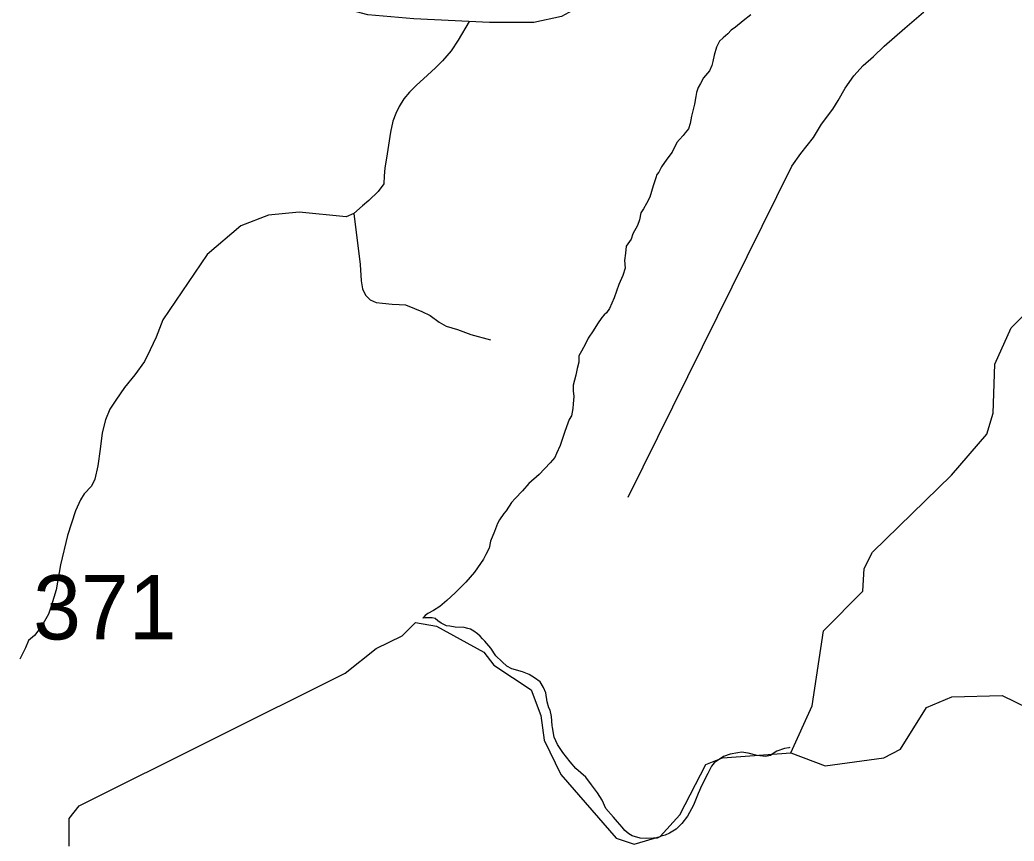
# Model space of a CAD drawing. Extents: x 2001466 to 2224147, y 644118 to 847247.
# Drawn here: x 2032460 to 2037534, y 689045 to 693236 of the extents above; entities that cross this region are included whole.
import ezdxf

# ---------------------------------------------------------------- set-up
doc = ezdxf.new("R2010")
doc.units = 0
for name, color, linetype in [('Exist Hydrographic Creek Single Shore', 7, 'Continuous'), ('Exist Hydrographic Misc Water Feature', 7, 'Continuous'), ('Exist Road Non-System Type 51', 7, 'Continuous'), ('Exist Road Secondary Structure Standard Bridge Number Label', 7, 'Continuous'), ('Exist Road Secondary Type 51 Attributed', 7, 'Continuous')]:
    doc.layers.add(name, color=color, linetype=linetype)

msp = doc.modelspace()

# ---------------------------------------------------------------- linework, layer by layer
at = {"layer": 'Exist Hydrographic Creek Single Shore'}
for points in [[(2032712.1, 689019), (2032712.1, 689160.1), (2032762.1, 689224.7), (2034120.2, 689902.4), (2034278.2, 690027.2), (2034411.1, 690093.4), (2034478.2, 690161), (2034586.2, 690142.3), (2034828.2, 690009.5), (2034878.2, 689942.8), (2035069.1, 689817.5), (2035119.2, 689685.3), (2035136.2, 689560.3), (2035220.1, 689384.6), (2035503, 689060.7), (2035595.1, 689029.2), (2035728.2, 689069.2), (2035828, 689178.7), (2035961.1, 689435.2), (2036045.2, 689469.6), (2036394.2, 689495.3)], [(2037215.8, 689780.5), (2037472.1, 689788.3), (2037605.2, 689723.3), (2037747.1, 689756.5), (2037946.2, 689949.3), (2038046.1, 689999.8), (2038229.2, 690022.3)], [(2036394.2, 689495.3), (2036569.1, 689429.4), (2036869.1, 689469.3), (2036953.2, 689513.5), (2037086, 689727.3), (2037215.8, 689780.5)]]:
    msp.add_lwpolyline(points, dxfattribs=at)
at = {"layer": 'Exist Hydrographic Misc Water Feature'}
for p, q in [((2037526.3, 691672.4), (2037803.4, 691955.3)), ((2036388.4, 689522.3), (2036384.5, 689520.3))]:
    msp.add_line(p, q, dxfattribs=at)
for points in [[(2036190.4, 693261.6), (2036150.4, 693231.6), (2036112.4, 693199.5), (2036090.3, 693183.5), (2036072.5, 693165.5), (2036048.5, 693143.6), (2036030.4, 693127.6), (2036014.4, 693097.5), (2036002.5, 693055.5), (2035996.6, 693023.5), (2035990.4, 693003.6), (2035978.5, 692975.6), (2035948.6, 692939.5), (2035932.6, 692911.5), (2035920.5, 692891.5), (2035912.5, 692865.5), (2035908.6, 692845.5), (2035902.7, 692805.5), (2035886.7, 692745.5), (2035880.7, 692707.5), (2035872.7, 692679.5), (2035854.7, 692659.5), (2035844.6, 692645.5), (2035826.8, 692625.5), (2035812.9, 692609.5), (2035788.9, 692561.5), (2035760.8, 692525.4), (2035734.9, 692485.4), (2035720.8, 692459.4), (2035710.7, 692447.4), (2035705, 692429.4), (2035691.1, 692389.4), (2035675.1, 692331.4), (2035657, 692299.4), (2035642.9, 692271.4), (2035628.9, 692251.4), (2035621.1, 692215.4), (2035611.1, 692187.4), (2035587.1, 692143.4), (2035579.1, 692117.4), (2035553.1, 692081.3), (2035551.2, 692045.4), (2035545.3, 692007.4), (2035549.2, 691969.4), (2035537.3, 691931.4), (2035517.2, 691885.4), (2035493.4, 691817.4), (2035469.4, 691763.4), (2035453.4, 691741.4), (2035441.3, 691731.4), (2035429.4, 691717.4), (2035407.5, 691685.3), (2035385.5, 691649.3), (2035359.5, 691611.4), (2035345.5, 691583.4), (2035325.4, 691545.3), (2035311.5, 691521.3), (2035311.5, 691489.3), (2035303.5, 691457.4), (2035297.6, 691423.4), (2035283.6, 691371.3), (2035283.6, 691343.4), (2035287.5, 691313.4), (2035283.6, 691277.3), (2035281.8, 691253.3)], [(2037214.6, 690912.3), (2037394.2, 691122), (2037427.2, 691229.6), (2037435.2, 691478.8), (2037518.3, 691664.2), (2037526.3, 691672.4)], [(2035281.8, 691253.3), (2035275.6, 691215.3), (2035263.7, 691197.4), (2035255.7, 691177.4), (2035241.6, 691135.3), (2035217.8, 691063.4), (2035197.9, 691023.4), (2035189.7, 691003.3), (2035165.7, 690975.3), (2035109.9, 690915.3), (2035057.9, 690869.3), (2035024, 690833.3), (2034987.9, 690793.2), (2034968, 690773.2), (2034942, 690731.2), (2034930.1, 690717.2), (2034908, 690685.2), (2034898.1, 690665.2), (2034882.1, 690625.2), (2034862.2, 690575.2), (2034854.2, 690539.2), (2034838.2, 690507.1), (2034826.1, 690483.2), (2034780.2, 690417.1), (2034736.3, 690367.2), (2034680.4, 690311.2), (2034638.3, 690273.1), (2034602.4, 690243.1), (2034570.4, 690221.1), (2034542.4, 690207), (2034528.4, 690197), (2034516.3, 690183)], [(2036394.2, 689495.3), (2036503.1, 689735.9), (2036561.1, 690118.6), (2036761.2, 690321.2), (2036769.2, 690435.9), (2036810.2, 690520.3), (2037214.6, 690912.3)], [(2036384.5, 689520.3), (2036362.6, 689518.3), (2036322.4, 689504.3), (2036304.6, 689492.3), (2036290.4, 689482.2), (2036264.6, 689476.2), (2036222.6, 689482.2), (2036176.4, 689494.2), (2036142.6, 689498.2), (2036124.5, 689496.1), (2036084.6, 689488.1), (2036050.7, 689476.1), (2036028.6, 689462.1), (2036002.5, 689444.1), (2035988.6, 689428.1), (2035970.5, 689390.1), (2035940.6, 689330), (2035920.7, 689288.1), (2035896.7, 689228), (2035866.8, 689172.1), (2035838.7, 689134.1), (2035809, 689106), (2035774.9, 689086), (2035752.8, 689076), (2035732.9, 689070), (2035712.8, 689060), (2035692.9, 689060), (2035658.9, 689057.9), (2035624.8, 689059.9), (2035584.8, 689071.9), (2035566.8, 689081.8), (2035546.9, 689099.9), (2035533, 689115.9), (2035509, 689143.8), (2035488.9, 689167.8), (2035450.7, 689211.8), (2035430.8, 689253.7), (2035406.9, 689291.7), (2035376.7, 689331.7), (2035348.8, 689371.7), (2035296.7, 689415.7), (2035268.9, 689449.6), (2035230.7, 689497.6), (2035202.6, 689537.6), (2035186.6, 689575.5), (2035178.6, 689625.5), (2035176.6, 689635.5), (2035172.7, 689681.6), (2035166.5, 689713.5), (2035158.7, 689725.5), (2035150.5, 689755.5), (2035144.6, 689801.5), (2035132.5, 689829.5), (2035114.5, 689857.5), (2035086.6, 689877.5), (2035058.5, 689895.4), (2035024.4, 689909.4), (2034970.5, 689923.4), (2034944.5, 689937.4), (2034920.5, 689959.3), (2034888.5, 689991.3), (2034862.4, 690029.3), (2034832.5, 690065.2), (2034820.4, 690077.2), (2034808.3, 690091.2), (2034794.4, 690103.2), (2034776.3, 690117.2), (2034760.3, 690127.2), (2034746.4, 690129.2), (2034726.5, 690135.1), (2034680.4, 690137.1), (2034654.3, 690141.1), (2034636.5, 690143.1), (2034610.4, 690157.1), (2034592.4, 690169.1), (2034578.4, 690181.1), (2034564.5, 690185.1), (2034542.4, 690185.1), (2034528.4, 690185), (2034516.3, 690183)]]:
    msp.add_lwpolyline(points, dxfattribs=at)
at = {"layer": 'Exist Road Non-System Type 51'}
for points in [[(2035564.2, 690800.7), (2036399, 692489.7), (2036444.9, 692553.8), (2036509, 692635.9), (2036550.8, 692703.8), (2036609, 692779.9), (2036634.9, 692823.9), (2036670.8, 692887.8), (2036714.8, 692949.9), (2036762.7, 693004), (2036816.7, 693049.9), (2036870.7, 693102), (2036976.6, 693194), (2037070.7, 693276.1), (2037152.6, 693366.1), (2037212.5, 693428.1), (2037257.7, 693439.1), (2037297.9, 693450.3), (2037330.1, 693457.7), (2037386.3, 693466.5), (2037428.4, 693471.7), (2037536.5, 693477.5)], [(2034753, 693227.4), (2034696.6, 693131.8), (2034660.7, 693077.7), (2034616.7, 693027.8), (2034580.7, 692991.7), (2034518.8, 692935.8), (2034484.7, 692903.7), (2034448.8, 692867.6), (2034418.7, 692833.6), (2034394.9, 692793.7), (2034378.7, 692757.6), (2034362.8, 692719.7), (2034350.8, 692663.6), (2034334.9, 692551.7), (2034322.9, 692479.7), (2034318.8, 692439.6), (2034316.8, 692399.6), (2034289, 692359.6), (2034240.9, 692313.6), (2034208.9, 692287.6), (2034164.9, 692247.5), (2034125, 692231.5)], [(2034125, 692231.5), (2033884.9, 692254.1), (2033728.5, 692239.4), (2033586.8, 692185.6), (2033415.9, 692039), (2033189.2, 691705.1), (2033155.4, 691617), (2033125.3, 691553), (2033095.2, 691493), (2033047.4, 691425), (2032993.3, 691359.1), (2032949.4, 691295), (2032919.4, 691249), (2032897.5, 691195), (2032879.4, 691129), (2032869.5, 691045), (2032857.6, 690961), (2032841.6, 690892.9), (2032825.6, 690856.9), (2032787.6, 690816.8), (2032769.6, 690787), (2032743.7, 690730.9), (2032703.7, 690604.9), (2032667.6, 690454.9), (2032645.8, 690326.9), (2032621.8, 690248.8), (2032605.9, 690202.9), (2032571.8, 690142.8), (2032533.9, 690094.7), (2032503.9, 690068.8), (2032488, 690030.9), (2032475.8, 690004.7), (2032460, 689972.8)], [(2034164.9, 692247.5), (2034197, 691987.4), (2034201.1, 691903.6), (2034209.1, 691863.6), (2034223, 691831.5), (2034246.8, 691808), (2034277.4, 691793), (2034311, 691789.5), (2034359.1, 691785.5), (2034395.1, 691783.6), (2034427, 691781.5), (2034473.1, 691763.6), (2034511.1, 691747.6), (2034553.1, 691727.8), (2034599, 691693.6), (2034635, 691673.7), (2034693.1, 691655.7), (2034761.1, 691629.7), (2034861, 691603.9)]]:
    msp.add_lwpolyline(points, dxfattribs=at)
at = {"layer": 'Exist Road Secondary Type 51 Attributed'}
msp.add_lwpolyline([(2038786.2, 694537.2), (2038720.8, 694490.7), (2038632.1, 694445.3), (2038545, 694421), (2038386.7, 694404.1), (2037558, 694403), (2037384.9, 694385.1), (2037093, 694314.3), (2036787.9, 694203.4), (2036363.1, 694023.8), (2036044.3, 693882.2), (2035928.1, 693808.3), (2035618.8, 693518.9), (2035355.5, 693325.5), (2035224.6, 693253.7), (2035083.1, 693222), (2034857.2, 693222), (2034469.8, 693242.1), (2034235.4, 693262.2), (2034087.1, 693300.2), (2033812.7, 693410), (2033624.8, 693460.8), (2033470.6, 693477.7), (2032848.5, 693515.5)], dxfattribs=at)

# ---------------------------------------------------------------- texts
at = {"layer": 'Exist Road Secondary Structure Standard Bridge Number Label'}
msp.add_text('371', height=328.08, dxfattribs=at).set_placement((2032527.7, 690074.2))

doc.saveas('drawing.dxf')
